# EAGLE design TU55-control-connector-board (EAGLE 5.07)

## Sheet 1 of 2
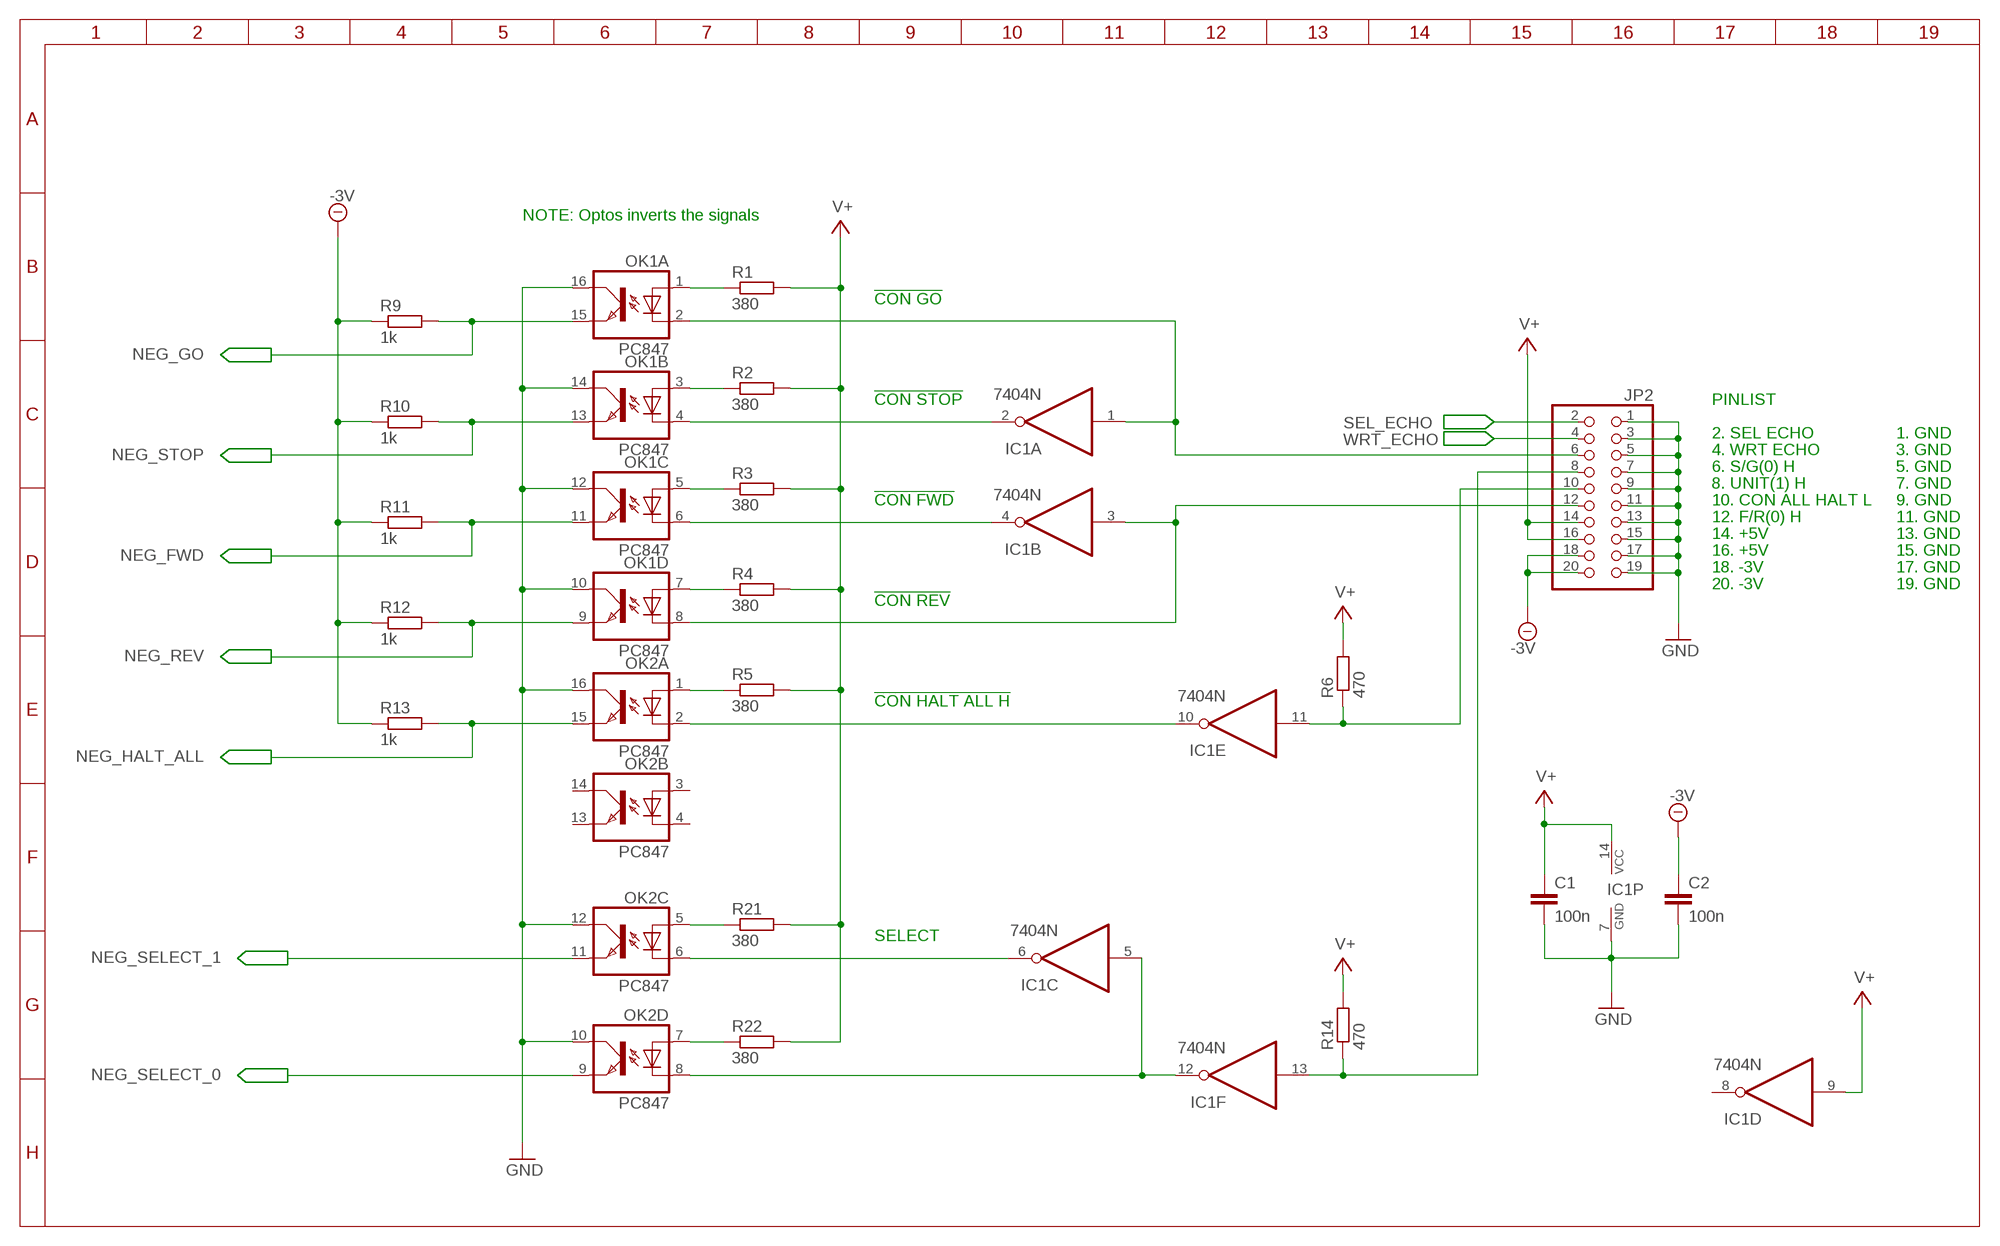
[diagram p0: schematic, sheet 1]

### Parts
C1  100n  C5/3.5  [C5B3.5]
C2  100n  C5/3.5  [C5B3.5]
IC1  7404N  [DIL14]
JP2  PINHD-2X10/90-FRAMED  [2Z10/90-FRAMED]
OK1  PC847  [DIL16]
OK2  PC847  [DIL16]
R1  380  R-EU_0207/10  [0207/10]
R2  380  R-EU_0207/10  [0207/10]
R3  380  R-EU_0207/10  [0207/10]
R4  380  R-EU_0207/10  [0207/10]
R5  380  R-EU_0207/10  [0207/10]
R6  470  R-EU_0207/10  [0207/10]
R9  1k  R-EU_0207/10  [0207/10]
R10  1k  R-EU_0207/10  [0207/10]
R11  1k  R-EU_0207/10  [0207/10]
R12  1k  R-EU_0207/10  [0207/10]
R13  1k  R-EU_0207/10  [0207/10]
R14  470  R-EU_0207/10  [0207/10]
R21  380  R-EU_0207/10  [0207/10]
R22  380  R-EU_0207/10  [0207/10]

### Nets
-3V: C2.1 JP2.18 JP2.20 R9.1 R10.1 R11.1 R12.1 R13.1 ; also sheet 2
GND: C1.2 C2.2 IC1.7(P:GND) JP2.1 JP2.3 JP2.5 JP2.7 JP2.9 JP2.11 JP2.13 JP2.15 JP2.17 JP2.19 OK1.10(D:COL) OK1.12(C:COL) OK1.14(B:COL) OK1.16(A:COL) OK2.10(D:COL) OK2.12(C:COL) OK2.16(A:COL)
N$1: IC1.10(E:O) OK2.2(A:C)
N$3: IC1.5(C:I) IC1.12(F:O) OK2.8(D:C)
N$4: IC1.11(E:I) JP2.10 R6.1
N$10: IC1.1(A:I) JP2.6 OK1.2(A:C)
N$11: IC1.2(A:O) OK1.4(B:C)
N$15: IC1.13(F:I) JP2.8 R14.1
N$23: IC1.4(B:O) OK1.6(C:C)
N$25: OK2.5(C:A) R21.1
N$26: OK2.7(D:A) R22.1
N$27: IC1.3(B:I) JP2.12 OK1.8(D:C)
N$28: OK2.1(A:A) R5.1
N$29: OK1.7(D:A) R4.1
N$30: OK1.5(C:A) R3.1
N$31: OK1.3(B:A) R2.1
N$32: OK1.1(A:A) R1.1
N$33: IC1.6(C:O) OK2.6(C:C)
NEG_FWD: OK1.11(C:EMIT) R11.2 ; also sheet 2
NEG_GO: OK1.15(A:EMIT) R9.2 ; also sheet 2
NEG_HALT_ALL: OK2.15(A:EMIT) R13.2 ; also sheet 2
NEG_REV: OK1.9(D:EMIT) R12.2 ; also sheet 2
NEG_SELECT_0: OK2.9(D:EMIT) ; also sheet 2
NEG_SELECT_1: OK2.11(C:EMIT) ; also sheet 2
NEG_STOP: OK1.13(B:EMIT) R10.2 ; also sheet 2
SEL_ECHO: JP2.2 ; also sheet 2
V+: C1.1 IC1.9(D:I) IC1.14(P:VCC) JP2.14 JP2.16 R1.2 R2.2 R3.2 R4.2 R5.2 R6.2 R14.2 R21.2 R22.2
WRT_ECHO: JP2.4 ; also sheet 2
Unconnected: IC1.8(D:O) OK2.3(B:A) OK2.4(B:C) OK2.13(B:EMIT) OK2.14(B:COL)

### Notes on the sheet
- NOTE: Optos inverts the signals
- !CON GO
- !CON STOP | PINLIST
- 2. SEL ECHO | 1. GND
- 4. WRT ECHO | 3. GND
- 6. S/G(0) H | 5. GND
- 8. UNIT(1) H | 7. GND
- !CON FWD | 10. CON ALL HALT L | 9. GND
- 12. F/R(0) H | 11. GND
- 14. +5V | 13. GND
- 16. +5V | 15. GND
- 18. -3V | 17. GND
- 20. -3V | 19. GND
- !CON REV
- !CON HALT ALL H
- SELECT

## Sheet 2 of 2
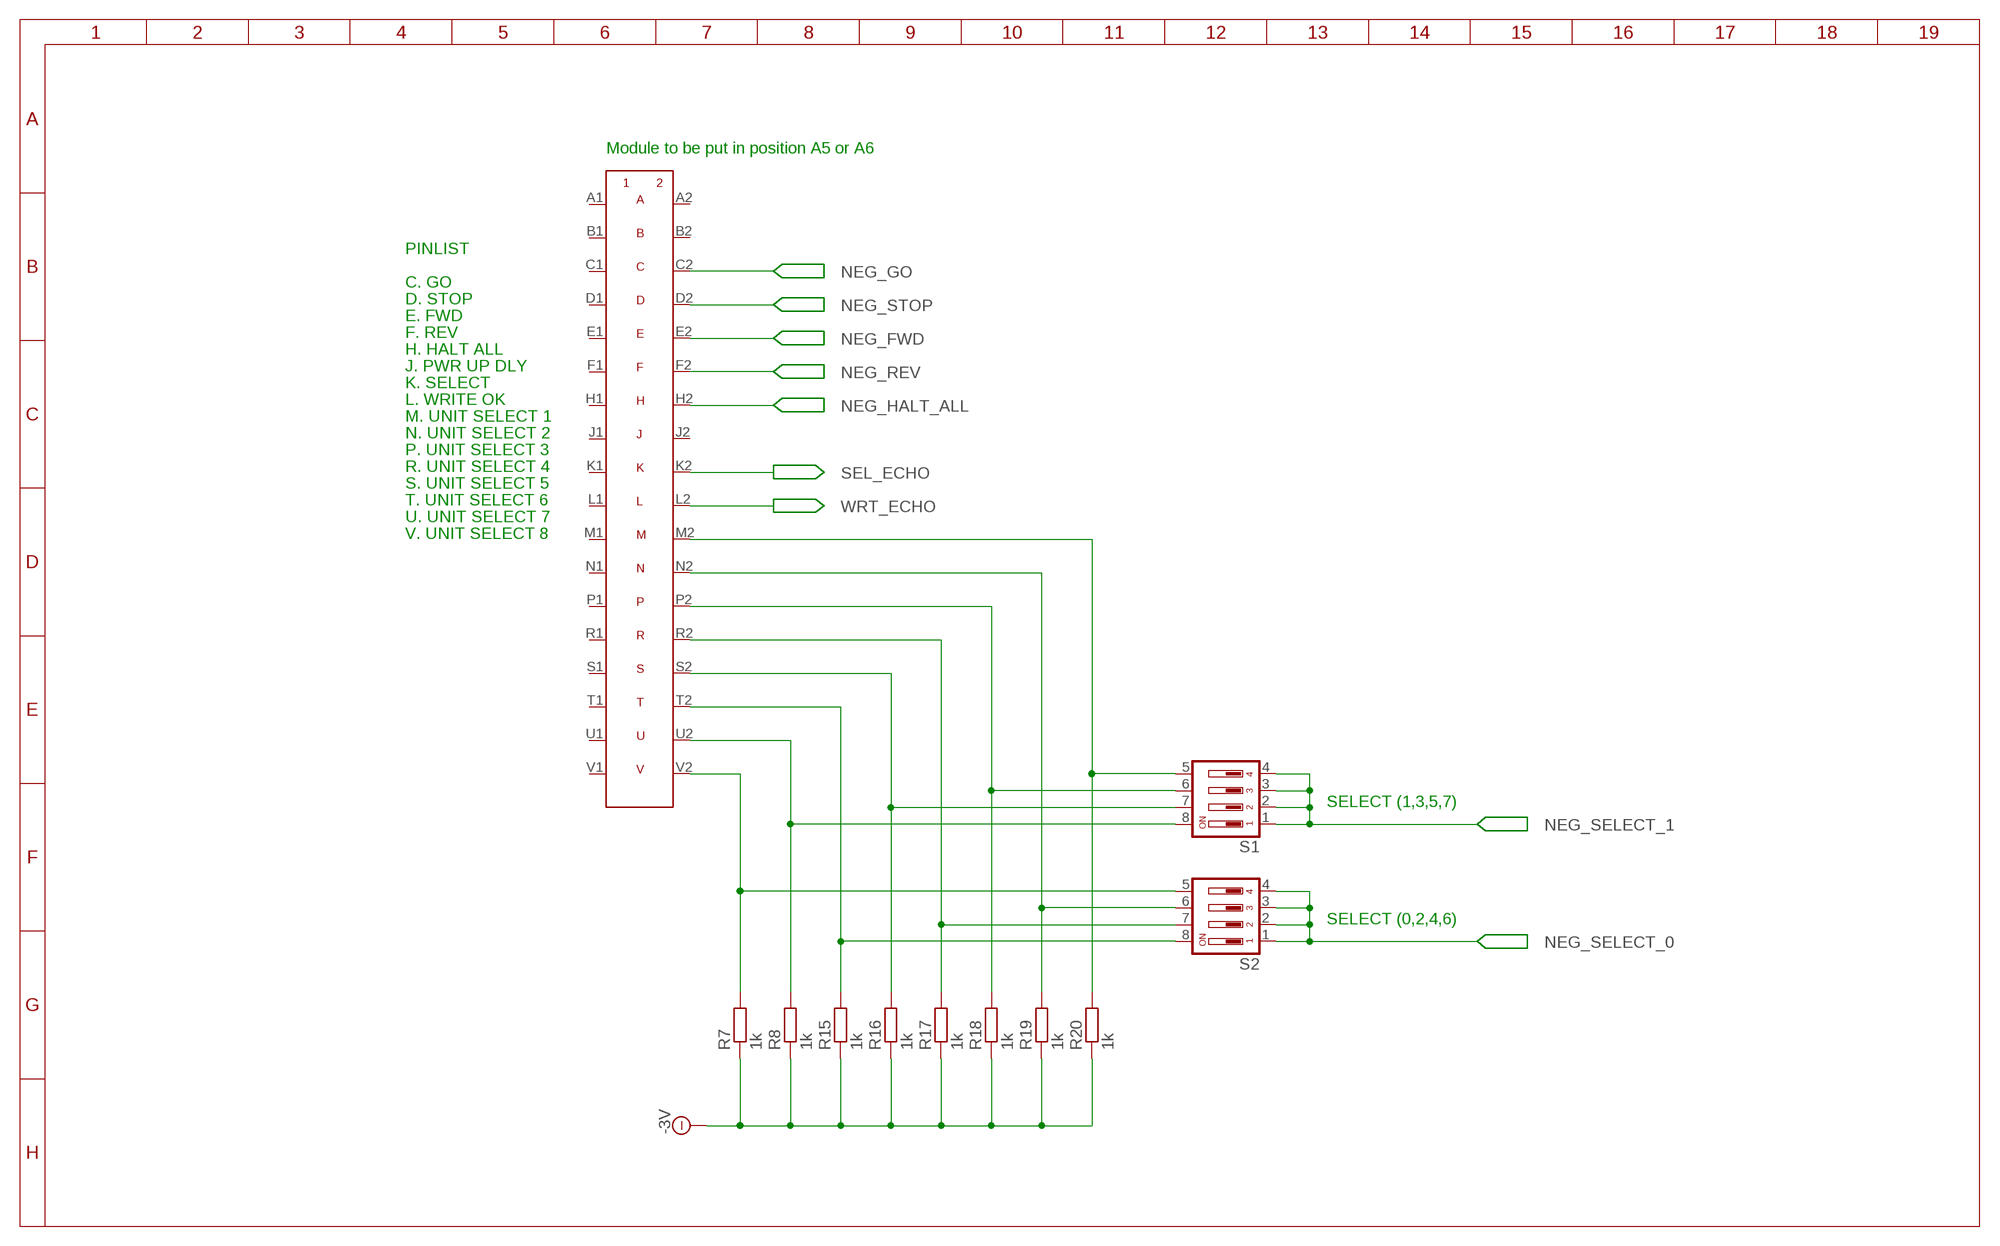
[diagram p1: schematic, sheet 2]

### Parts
CON1  FLIPCHIP_1NORMAL  [FLIPCHIP-1]
R7  1k  R-EU_0207/10  [0207/10]
R8  1k  R-EU_0207/10  [0207/10]
R15  1k  R-EU_0207/10  [0207/10]
R16  1k  R-EU_0207/10  [0207/10]
R17  1k  R-EU_0207/10  [0207/10]
R18  1k  R-EU_0207/10  [0207/10]
R19  1k  R-EU_0207/10  [0207/10]
R20  1k  R-EU_0207/10  [0207/10]
S1  DIP04YL  [DIP04YL]
S2  DIP04YL  [DIP04YL]

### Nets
-3V: R7.1 R8.1 R15.1 R16.1 R17.1 R18.1 R19.1 R20.1 ; also sheet 1
N$5: CON1.R2 R17.2 S2.7
N$6: CON1.T2 R15.2 S2.8
N$7: CON1.M2 R20.2 S1.5
N$8: CON1.V2 R7.2 S2.5
N$13: CON1.P2 R18.2 S1.6
N$14: CON1.N2 R19.2 S2.6
N$17: CON1.S2 R16.2 S1.7
N$20: CON1.U2 R8.2 S1.8
NEG_FWD: CON1.E2 ; also sheet 1
NEG_GO: CON1.C2 ; also sheet 1
NEG_HALT_ALL: CON1.H2 ; also sheet 1
NEG_REV: CON1.F2 ; also sheet 1
NEG_SELECT_0: S2.1 S2.2 S2.3 S2.4 ; also sheet 1
NEG_SELECT_1: S1.1 S1.2 S1.3 S1.4 ; also sheet 1
NEG_STOP: CON1.D2 ; also sheet 1
SEL_ECHO: CON1.K2 ; also sheet 1
WRT_ECHO: CON1.L2 ; also sheet 1
Unconnected: CON1.A1 CON1.A2 CON1.B1 CON1.B2 CON1.C1 CON1.D1 CON1.E1 CON1.F1 CON1.H1 CON1.J1 CON1.J2 CON1.K1 CON1.L1 CON1.M1 CON1.N1 CON1.P1 CON1.R1 CON1.S1 CON1.T1 CON1.U1 CON1.V1

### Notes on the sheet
- Module to be put in position A5 or A6
- PINLIST
- C. GO
- D. STOP
- E. FWD
- F. REV
- H. HALT ALL
- J. PWR UP DLY
- K. SELECT
- L. WRITE OK
- M. UNIT SELECT 1
- N. UNIT SELECT 2
- P. UNIT SELECT 3
- R. UNIT SELECT 4
- S. UNIT SELECT 5
- T. UNIT SELECT 6
- U. UNIT SELECT 7
- V. UNIT SELECT 8
- SELECT (1,3,5,7)
- SELECT (0,2,4,6)

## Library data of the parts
C1 C2 = anders:C: CAPACITOR
CON1 = anders:FLIPCHIP_1: DEC Digital equipment single flipchip
IC1 = 74xx-eu:74*04: Hex INVERTER
JP2 = pinhead:PINHD-2X10: PIN HEADER
OK1 OK2 = optocoupler:PC847: SHARP OPTO COUPLER
R1-R22 = anders:R-EU_: RESISTOR, European symbol
S1 S2 = switch-dil:DIP04YL: DIL/CODE SWITCH

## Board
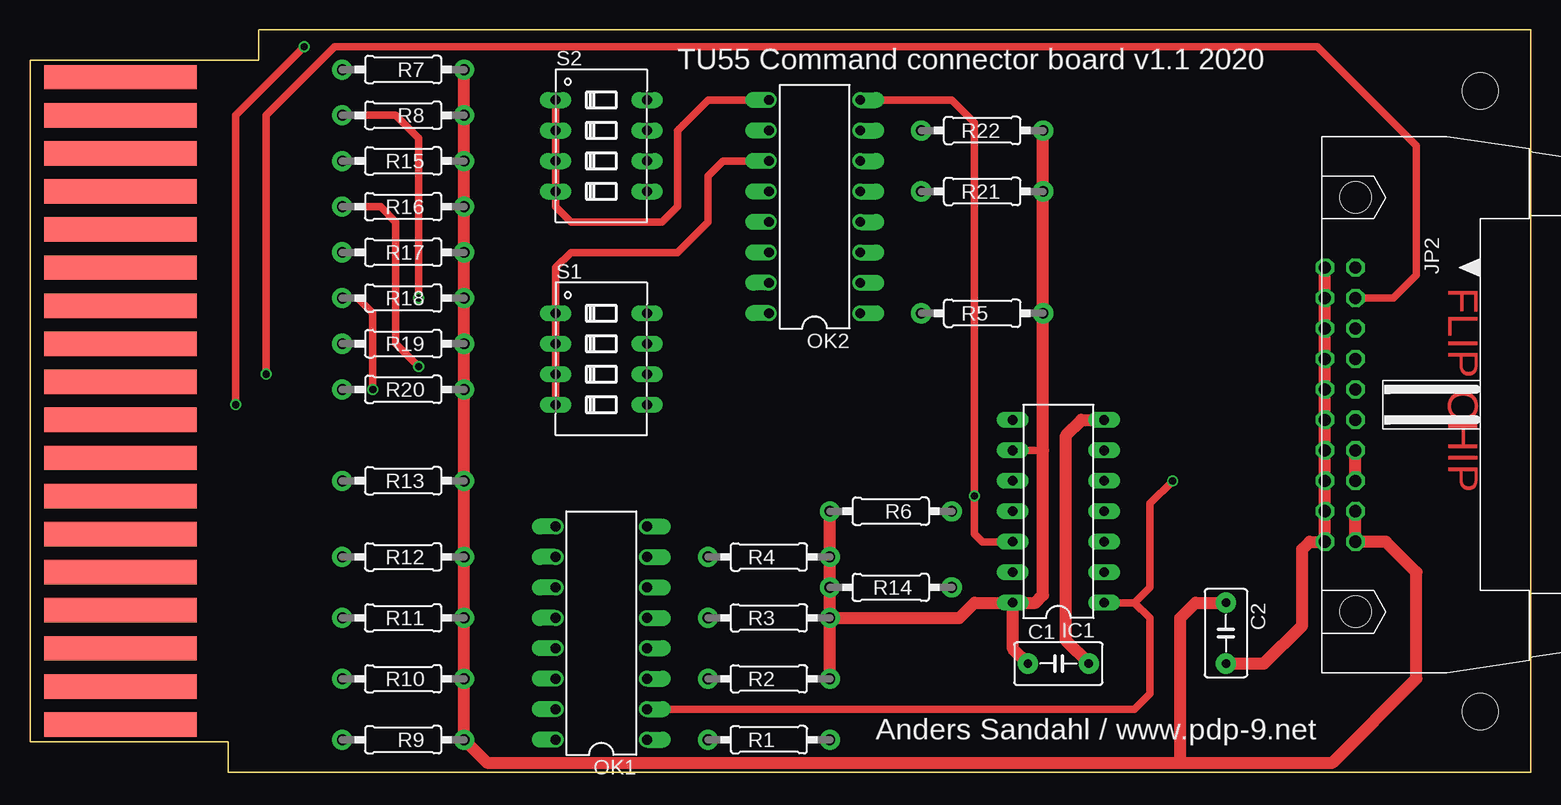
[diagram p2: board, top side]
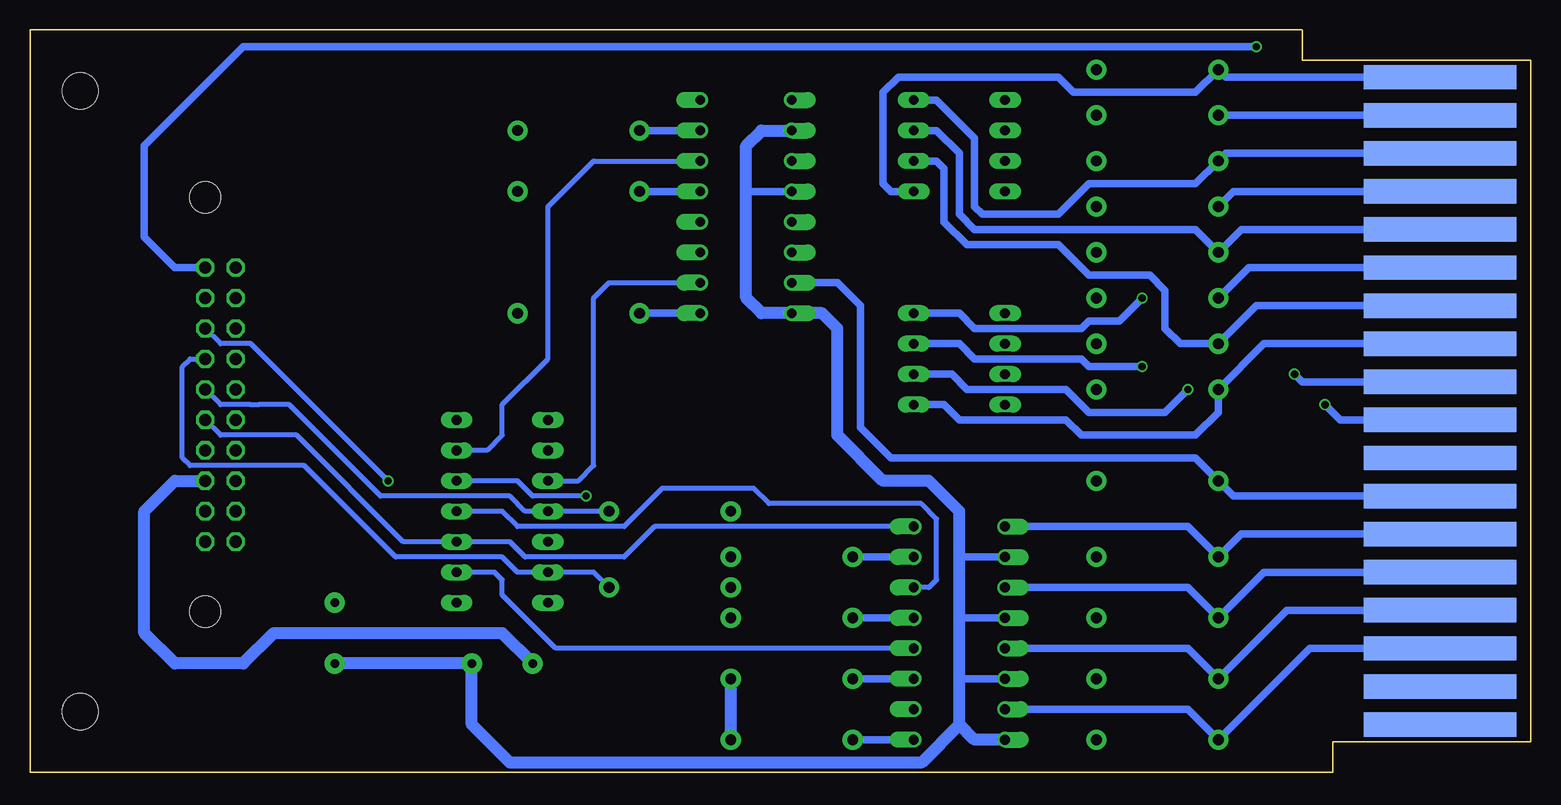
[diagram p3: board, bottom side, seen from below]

Size 125.09 x 61.91 mm. Coordinates in mm from the lower left corner, seen from the top.
Copper layers (1*16): Top 0.035mm / dielectric 1.5mm / Bottom 0.035mm
Design rules "SeeedStudio_2layer_DRU_no_angle_20140221": minimum track width 6mil, minimum drill 12mil, track to track 6mil, track to pad 6mil, pad to pad 6mil, via to via 6mil, smd to smd 0mil, copper to edge 10mil, drill to drill 10mil, minimum pad ring 10mil, minimum via ring 6mil, stop-mask expansion 2mil, vias tented up to drill 100mil, thermal gap 10mil

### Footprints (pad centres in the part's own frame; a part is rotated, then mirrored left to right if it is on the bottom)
C5B3.5 = drill 0.7 pad 1.676 round: 1 -2.54,0; 2 2.54,0
FLIPCHIP-1 = smd 12.7 x 2.032: A1 0.572,0; B1 0.572,3.175; C1 0.572,6.35; D1 0.572,9.525; E1 0.572,12.7; F1 0.572,15.875; H1 0.572,19.05; J1 0.572,22.225; K1 0.572,25.4; L1 0.572,28.575; M1 0.572,31.75; N1 0.572,34.925; P1 0.572,38.1; R1 0.572,41.275; S1 0.572,44.45; T1 0.572,47.625; U1 0.572,50.8; V1 0.572,53.975 | smd 12.7 x 2.032 bottom: A2 0.572,0; B2 0.572,3.175; C2 0.572,6.35; D2 0.572,9.525; E2 0.572,12.7; F2 0.572,15.875; H2 0.572,19.05; J2 0.572,22.225; K2 0.572,25.4; L2 0.572,28.575; M2 0.572,31.75; N2 0.572,34.925; P2 0.572,38.1; R2 0.572,41.275; S2 0.572,44.45; T2 0.572,47.625; U2 0.572,50.8; V2 0.572,53.975 | hole 3: 113.919,52.832; 113.919,1.079
DIL14 = drill 0.813 long: 1 -7.62,-3.81; 2 -5.08,-3.81; 3 -2.54,-3.81; 4 0,-3.81; 5 2.54,-3.81; 6 5.08,-3.81; 7 7.62,-3.81; 8 7.62,3.81; 9 5.08,3.81; 10 2.54,3.81; 11 0,3.81; 12 -2.54,3.81; 13 -5.08,3.81; 14 -7.62,3.81
2Z10/90-FRAMED = drill 1.016 octagon: 1 -11.43,-6.35; 2 -11.43,-3.81; 3 -8.89,-6.35; 4 -8.89,-3.81; 5 -6.35,-6.35; 6 -6.35,-3.81; 7 -3.81,-6.35; 8 -3.81,-3.81; 9 -1.27,-6.35; 10 -1.27,-3.81; 11 1.27,-6.35; 12 1.27,-3.81; 13 3.81,-6.35; 14 3.81,-3.81; 15 6.35,-6.35; 16 6.35,-3.81; 17 8.89,-6.35; 18 8.89,-3.81; 19 11.43,-6.35; 20 11.43,-3.81 | hole 2.6: 17.272,-3.81; -17.272,-3.81
DIL16 = drill 0.813 offset: 1 -8.89,-3.81; 2 -6.35,-3.81; 3 -3.81,-3.81; 4 -1.27,-3.81; 5 1.27,-3.81; 6 3.81,-3.81; 7 6.35,-3.81; 8 8.89,-3.81; 9 8.89,3.81; 10 6.35,3.81; 11 3.81,3.81; 12 1.27,3.81; 13 -1.27,3.81; 14 -3.81,3.81; 15 -6.35,3.81; 16 -8.89,3.81
0207/10 = drill 0.9 pad 1.676 round: 1 -5.08,0; 2 5.08,0
DIP04YL = drill 0.813 long: 1 -3.81,-3.81; 2 -1.27,-3.81; 3 1.27,-3.81; 4 3.81,-3.81; 5 3.81,3.81; 6 1.27,3.81; 7 -1.27,3.81; 8 -3.81,3.81

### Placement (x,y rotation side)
C1  85.72,9.08 0 top
C2  99.69,11.62 270 top
CON1  6.99,4 0 top
IC1  85.72,21.78 90 top
JP2  114.3,30.67 270 top
OK1  47.62,11.62 90 top
OK2  65.41,47.18 90 top
R1  61.59,2.73 0 top
R2  61.59,7.81 0 top
R3  61.59,12.89 0 top
R4  61.59,17.97 0 top
R5  79.38,38.29 0 top
R6  71.75,21.78 180 top
R7  31.12,58.61 180 top
R8  31.12,54.8 180 top
R9  31.12,2.73 180 top
R10  31.12,7.81 180 top
R11  31.12,12.89 180 top
R12  31.12,17.97 180 top
R13  31.12,24.32 180 top
R14  71.75,15.43 180 top
R15  31.12,50.99 180 top
R16  31.12,47.18 180 top
R17  31.12,43.37 180 top
R18  31.12,39.56 180 top
R19  31.12,35.75 180 top
R20  31.12,31.94 180 top
R21  79.38,48.45 0 top
R22  79.38,53.53 0 top
S1  47.62,34.48 270 top
S2  47.62,52.26 270 top

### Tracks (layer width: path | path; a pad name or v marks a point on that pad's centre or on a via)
-3V
  Top 0.61: R11.1 R10.1 R9.1
  Top 1.016: R7.1 R8.1 R15.1 R16.1 R17.1 R18.1 R19.1 R20.1 R13.1 R12.1 R11.1 R9.1 38.1,0.83 95.88,0.83 | 95.88,0.83 108.58,0.83 115.57,7.81 115.57,16.7 113.03,19.24 JP2.20 JP2.18 | C2.1 97.16,14.16 95.88,12.89 95.88,0.83
GND
  Top 1.016: C1.2 86.36,10.99 86.36,28.13 87.63,29.4 IC1.7 | JP2.1 JP2.3 JP2.5 JP2.7 JP2.9 JP2.11 JP2.13 JP2.15 JP2.17 JP2.19 106.68,19.24 106.05,18.61 106.05,12.26 102.87,9.08 C2.2
  Bottom 0.61: 47.62,17.97 OK1.10 | 47.62,7.81 OK1.14 | 47.62,12.89 OK1.12 | 65.41,48.45 OK2.12
  Bottom 1.016: 47.62,4 47.62,7.81 47.62,12.89 47.62,17.97 47.62,21.78 50.16,24.32 53.98,24.32 57.79,28.13 57.79,37.02 59.05,38.29 OK2.16 64.13,38.29 65.41,39.56 65.41,48.45 65.41,52.26 64.13,53.53 OK2.10 | 47.62,4 46.36,2.73 OK1.16 | C2.2 C1.2 88.27,4 85.09,0.83 50.8,0.83 47.62,4
N$1
  Bottom 0.406: IC1.10 79.38,24.32 78.1,25.59 78.1,39.56 76.83,40.83 OK2.2
N$3  (via drill 0.6)
  Top 0.61: IC1.12 79.38,19.24 78.74,19.88 v78.74,23.05 78.74,54.17 76.83,56.07 OK2.8
  Bottom 0.406: IC1.5 84.45,24.32 83.18,23.05 v78.74,23.05
N$4
  Bottom 0.406: R6.1 IC1.11 83.82,21.78 85.09,23.05 95.88,23.05 103.5,30.67 106.05,30.67 106.68,30.67 109.22,30.67 JP2.10
N$5
  Bottom 0.61: CON1.R2 24.13,45.28 R17.2 27.94,45.28 46.36,45.28 47.62,46.55 47.62,51.63 49.53,53.53 S2.7
N$6
  Bottom 0.61: CON1.T2 25.4,51.63 R15.2 27.94,49.09 36.83,49.09 39.37,46.55 45.72,46.55 46.36,47.18 46.36,52.9 49.53,56.07 S2.8
N$7
  Bottom 0.61: CON1.M2 22.23,35.75 R20.2 26.04,30.04 27.94,28.13 37.47,28.13 38.73,29.4 47.62,29.4 48.9,30.67 S1.5
N$8
  Bottom 0.61: CON1.V2 25.4,57.98 R7.2 27.94,56.71 38.1,56.71 39.37,57.98 52.71,57.98 53.98,56.71 53.98,49.09 53.34,48.45 S2.5
N$10  (via drill 0.6)
  Top 0.61: OK1.2 92.07,5.27 93.34,6.54 93.34,12.89 92.07,14.16 | 92.07,14.16 IC1.1 | 92.07,14.16 93.34,15.43 93.34,22.42 v95.25,24.32
  Bottom 0.406: JP2.6 109.22,35.75 106.68,35.75 v95.25,24.32
N$11
  Bottom 0.406: OK1.4 81.28,10.35 85.72,14.8 85.72,16.07 86.36,16.7 IC1.2
N$13  (via drill 0.6)
  Top 0.61: v28.58,31.94 28.58,38.29 27.3,39.56 R18.2
  Bottom 0.61: CON1.P2 23.49,42.1 R18.2 | S1.6 48.26,33.21 46.99,31.94 38.73,31.94 36.83,30.04 30.48,30.04 v28.58,31.94
N$14
  Bottom 0.61: CON1.N2 22.86,38.93 R19.2 29.21,35.75 30.48,37.02 30.48,40.2 31.75,41.47 36.83,41.47 39.37,44.01 46.99,44.01 48.9,45.91 48.9,50.36 49.53,50.99 S2.6
N$15
  Bottom 0.406: R14.1 78.1,16.7 IC1.13 84.45,16.7 85.72,17.97 94.61,17.97 102.23,25.59 111.76,25.59 112.39,26.23 112.39,33.85 111.76,34.48 JP2.8
N$17  (via drill 0.6)
  Top 0.61: R16.2 29.21,47.18 30.48,45.91 30.48,35.75 v32.39,33.85
  Bottom 0.61: CON1.S2 24.77,48.45 R16.2 | S1.7 47.62,35.75 46.36,34.48 37.47,34.48 36.83,33.85 33.66,33.85 v32.39,33.85
N$20  (via drill 0.6)
  Top 0.61: v32.39,39.56 32.39,52.9 30.48,54.8 R8.2
  Bottom 0.61: CON1.U2 R8.2 | S1.8 47.62,38.29 46.36,37.02 37.47,37.02 36.83,37.66 34.29,37.66 v32.39,39.56
N$23
  Bottom 0.406: IC1.4 85.72,21.78 84.45,20.51 75.56,20.51 72.39,23.69 64.77,23.69 63.5,22.42 50.8,22.42 49.53,21.15 49.53,16.07 50.16,15.43 OK1.6
N$25
  Bottom 0.61: OK2.5 R21.1
N$26
  Bottom 0.61: OK2.7 R22.1
N$27
  Bottom 0.406: OK1.8 73.02,20.51 75.56,17.97 83.82,17.97 85.09,19.24 IC1.3 93.98,19.24 102.87,28.13 109.22,28.13 JP2.12
N$28
  Bottom 0.61: OK2.1 R5.1
N$29
  Bottom 0.61: OK1.7 R4.1
N$30
  Bottom 0.61: OK1.5 R3.1
N$31
  Bottom 0.61: OK1.3 R2.1
N$32
  Bottom 0.61: OK1.1 R1.1
N$33
  Bottom 0.406: OK2.6 78.1,50.99 81.91,47.18 81.91,34.48 85.72,30.67 85.72,28.13 86.99,26.86 IC1.6
NEG_FWD
  Bottom 0.61: CON1.E2 22.23,16.7 R11.2 28.58,15.43 OK1.11
NEG_GO
  Bottom 0.61: CON1.C2 18.41,10.35 R9.2 28.58,5.27 OK1.15
NEG_HALT_ALL
  Bottom 0.61: CON1.H2 24.77,23.05 R13.2 27.94,26.23 53.34,26.23 55.88,28.77 55.88,38.93 57.79,40.83 OK2.15
NEG_REV
  Bottom 0.61: CON1.F2 24.13,19.88 R12.2 28.58,20.51 OK1.9
NEG_SELECT_0
  Top 0.61: S2.1 S2.2 S2.3 S2.4 43.82,47.18 45.09,45.91 52.71,45.91 53.98,47.18 53.98,53.53 56.52,56.07 OK2.9
NEG_SELECT_1
  Top 0.61: S1.4 S1.3 S1.2 S1.1 43.82,42.1 45.09,43.37 53.98,43.37 56.52,45.91 56.52,49.72 57.79,50.99 OK2.11
NEG_STOP
  Bottom 0.61: CON1.D2 20.32,13.53 R10.2 28.58,10.35 OK1.13
SEL_ECHO  (via drill 0.6)
  Top 0.61: v17.15,30.67 17.15,54.8 v22.86,60.52
  Bottom 0.61: CON1.K2 15.88,29.4 v17.15,30.67 | JP2.2 113.03,42.1 115.57,44.64 115.57,52.26 107.31,60.52 v22.86,60.52
V+
  Top 0.61: 84.45,26.86 IC1.9
  Top 1.016: R2.2 R3.2 | R3.2 R14.2 R4.2 R6.2 | R22.2 R21.2 R5.2 84.45,26.86 84.45,14.8 83.82,14.16 IC1.14 | JP2.16 JP2.14 | IC1.14 81.91,10.35 C1.1 | IC1.14 78.74,14.16 77.47,12.89 R3.2
  Bottom 1.016: R1.2 R2.2 | C1.1 85.72,11.62 104.77,11.62 107.31,9.08 113.03,9.08 115.57,11.62 115.57,21.78 113.03,24.32 JP2.16
WRT_ECHO  (via drill 0.6)
  Top 0.61: v19.69,33.21 19.69,54.8 25.4,60.52 107.31,60.52 115.57,52.26 115.57,41.47 113.66,39.56 JP2.4
  Bottom 0.61: CON1.L2 19.05,32.58 v19.69,33.21

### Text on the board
tNames: TU55 Command connector board v1.1 2020 | Anders Sandahl / www.pdp-9.net
tDocu: 6 | 4 | 2 | 0 (8) | 7 | 5 | 3 | 1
